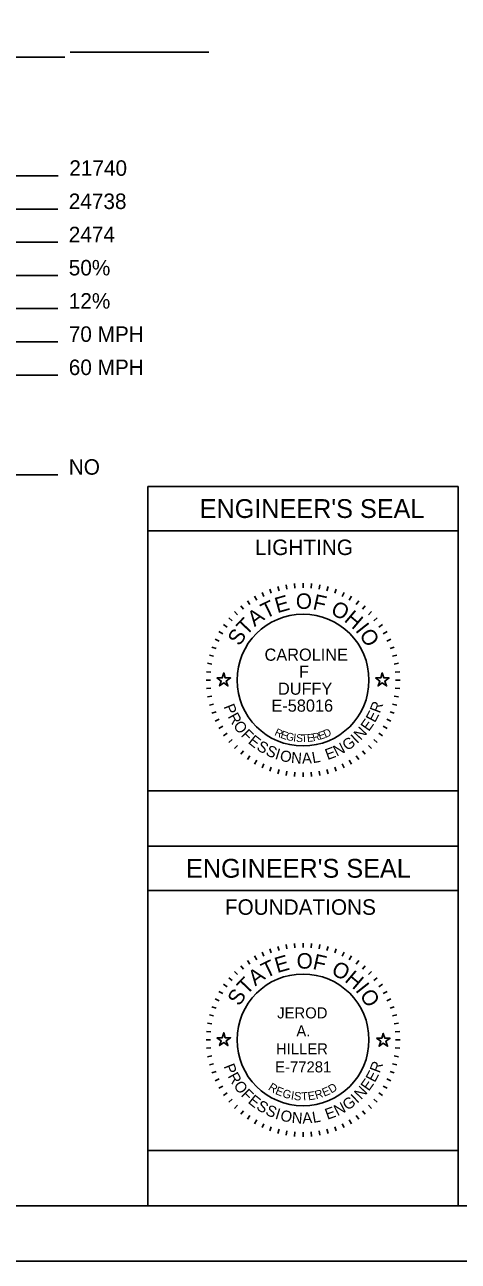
# Model space of a CAD drawing. Extents: x 0 to 51, y -1.2 to 22.
# Drawn here: x 7.34 to 11.25, y 0 to 11.17 of the extents above; entities that cross this region are included whole.
import ezdxf

# ---------------------------------------------------------------- set-up
doc = ezdxf.new("R2010")
doc.units = 0
for name, color, linetype in [('Default', 7, 'Continuous'), ('SH_Border', 7, 'Continuous'), ('SH_Cut_Line', 7, 'Continuous'), ('SH_Data', 7, 'Continuous'), ('SH_Text', 7, 'Continuous')]:
    doc.layers.add(name, color=color, linetype=linetype)

msp = doc.modelspace()

# ---------------------------------------------------------------- linework, layer by layer
at = {"layer": 'Default'}
for points in [[(9.074, 5.27), (9.121, 5.27), (9.135, 5.315), (9.149, 5.27), (9.196, 5.27), (9.158, 5.242), (9.173, 5.198), (9.135, 5.225), (9.097, 5.198), (9.112, 5.242)], [(10.504, 5.27), (10.551, 5.27), (10.565, 5.315), (10.579, 5.27), (10.626, 5.27), (10.588, 5.242), (10.603, 5.198), (10.565, 5.225), (10.527, 5.198), (10.542, 5.242)]]:
    msp.add_lwpolyline(points, close=True, dxfattribs=at)
at = {"layer": 'SH_Border'}
msp.add_lwpolyline([(1.5, 21.5), (33.5, 21.5), (33.5, 0.5), (1.5, 0.5)], close=True, dxfattribs=at)
at = {"layer": 'SH_Cut_Line'}
msp.add_lwpolyline([(0, 0), (34, 0), (34, 22), (0, 22)], close=True, dxfattribs=at)
at = {"layer": 'SH_Data'}
for p, q in [((8.45, 3.75), (8.45, 7)), ((8.45, 7), (11.25, 7)), ((11.25, 7), (11.25, 3.75)), ((8.45, 6.6), (11.25, 6.6)), ((9.48, 6.043), (9.497, 6.007)), ((9.551, 6.072), (9.564, 6.035)), ((9.624, 6.095), (9.634, 6.057)), ((9.698, 6.112), (9.705, 6.072)), ((9.774, 6.122), (9.777, 6.082)), ((9.85, 6.125), (9.85, 6.085)), ((9.926, 6.122), (9.923, 6.082)), ((10.002, 6.112), (9.995, 6.072)), ((10.076, 6.095), (10.066, 6.057)), ((10.149, 6.072), (10.136, 6.035)), ((10.22, 6.043), (10.203, 6.007)), ((9.348, 5.967), (9.371, 5.934)), ((9.413, 6.008), (9.433, 5.973)), ((10.287, 6.008), (10.267, 5.973)), ((10.352, 5.967), (10.329, 5.934)), ((11.25, 3.75), (11.25, 5.921)), ((9.18, 5.812), (9.21, 5.787)), ((9.231, 5.869), (9.26, 5.84)), ((9.288, 5.92), (9.313, 5.89)), ((10.412, 5.92), (10.387, 5.89)), ((10.469, 5.869), (10.44, 5.84)), ((10.52, 5.812), (10.49, 5.787)), ((9.133, 5.752), (9.166, 5.729)), ((10.567, 5.752), (10.534, 5.729)), ((9.057, 5.62), (9.093, 5.603)), ((9.092, 5.688), (9.127, 5.668)), ((10.608, 5.688), (10.573, 5.668)), ((10.643, 5.62), (10.607, 5.603)), ((9.005, 5.476), (9.043, 5.466)), ((9.028, 5.549), (9.065, 5.536)), ((10.672, 5.549), (10.635, 5.536)), ((10.695, 5.476), (10.657, 5.466)), ((8.988, 5.402), (9.028, 5.395)), ((10.712, 5.402), (10.672, 5.395)), ((8.978, 5.326), (9.018, 5.323)), ((10.722, 5.326), (10.682, 5.323)), ((8.975, 5.25), (9.015, 5.25)), ((8.978, 5.174), (9.018, 5.177)), ((10.722, 5.174), (10.682, 5.177)), ((10.725, 5.25), (10.685, 5.25)), ((8.988, 5.098), (9.028, 5.105)), ((9.005, 5.024), (9.043, 5.034)), ((10.695, 5.024), (10.657, 5.034)), ((10.712, 5.098), (10.672, 5.105)), ((9.028, 4.951), (9.065, 4.964)), ((10.672, 4.951), (10.635, 4.964)), ((9.057, 4.88), (9.093, 4.897)), ((9.092, 4.813), (9.127, 4.833)), ((10.608, 4.813), (10.573, 4.833)), ((10.643, 4.88), (10.607, 4.897)), ((9.133, 4.748), (9.166, 4.771)), ((9.18, 4.688), (9.21, 4.713)), ((10.52, 4.688), (10.49, 4.713)), ((10.567, 4.748), (10.534, 4.771)), ((9.231, 4.631), (9.26, 4.66)), ((9.288, 4.58), (9.313, 4.61)), ((10.412, 4.58), (10.387, 4.61)), ((10.469, 4.631), (10.44, 4.66)), ((9.348, 4.533), (9.371, 4.566)), ((9.413, 4.492), (9.433, 4.527)), ((9.48, 4.457), (9.497, 4.493)), ((10.22, 4.457), (10.203, 4.493)), ((10.287, 4.492), (10.267, 4.527)), ((10.352, 4.533), (10.329, 4.566)), ((9.551, 4.428), (9.564, 4.465)), ((9.624, 4.405), (9.634, 4.443)), ((9.698, 4.388), (9.705, 4.428)), ((9.774, 4.378), (9.777, 4.418)), ((9.85, 4.375), (9.85, 4.415)), ((9.926, 4.378), (9.923, 4.418)), ((10.002, 4.388), (9.995, 4.428)), ((10.076, 4.405), (10.066, 4.443)), ((10.149, 4.428), (10.136, 4.465)), ((11.25, 3.75), (8.45, 3.75)), ((8.45, 3.75), (8.45, 0.5)), ((11.25, 3.75), (8.45, 3.75)), ((8.45, 3.75), (11.25, 3.75)), ((11.25, 0.5), (11.25, 3.75)), ((11.25, 3.35), (8.45, 3.35)), ((9.48, 2.793), (9.497, 2.757)), ((9.551, 2.822), (9.564, 2.785)), ((9.624, 2.845), (9.634, 2.807)), ((9.698, 2.862), (9.705, 2.822)), ((9.774, 2.872), (9.777, 2.832)), ((9.85, 2.875), (9.85, 2.835)), ((9.926, 2.872), (9.923, 2.832)), ((10.002, 2.862), (9.995, 2.822)), ((10.076, 2.845), (10.066, 2.807)), ((10.149, 2.822), (10.136, 2.785)), ((10.22, 2.793), (10.203, 2.757)), ((9.348, 2.717), (9.371, 2.684)), ((9.413, 2.758), (9.433, 2.723)), ((10.287, 2.758), (10.267, 2.723)), ((10.352, 2.717), (10.329, 2.684)), ((9.231, 2.619), (9.26, 2.59)), ((9.288, 2.67), (9.313, 2.64)), ((10.412, 2.67), (10.387, 2.64)), ((10.469, 2.619), (10.44, 2.59)), ((9.133, 2.502), (9.166, 2.479)), ((9.18, 2.562), (9.21, 2.537)), ((10.52, 2.562), (10.49, 2.537)), ((10.567, 2.502), (10.534, 2.479)), ((9.057, 2.37), (9.093, 2.353)), ((9.092, 2.438), (9.127, 2.418)), ((10.608, 2.438), (10.573, 2.418)), ((10.643, 2.37), (10.607, 2.353)), ((9.028, 2.299), (9.065, 2.286)), ((10.672, 2.299), (10.635, 2.286)), ((8.988, 2.152), (9.028, 2.145)), ((9.005, 2.226), (9.043, 2.216)), ((10.695, 2.226), (10.657, 2.216)), ((10.712, 2.152), (10.672, 2.145)), ((8.978, 2.076), (9.018, 2.073)), ((10.722, 2.076), (10.682, 2.073)), ((8.975, 2), (9.015, 2)), ((8.978, 1.924), (9.018, 1.927)), ((10.722, 1.924), (10.682, 1.927)), ((10.725, 2), (10.685, 2)), ((8.988, 1.848), (9.028, 1.855)), ((10.712, 1.848), (10.672, 1.855)), ((9.005, 1.774), (9.043, 1.784)), ((9.028, 1.701), (9.065, 1.714)), ((10.672, 1.701), (10.635, 1.714)), ((10.695, 1.774), (10.657, 1.784)), ((9.057, 1.63), (9.093, 1.647)), ((9.092, 1.563), (9.127, 1.583)), ((10.608, 1.563), (10.573, 1.583)), ((10.643, 1.63), (10.607, 1.647)), ((9.133, 1.498), (9.166, 1.521)), ((9.18, 1.438), (9.21, 1.463)), ((10.52, 1.438), (10.49, 1.463)), ((10.567, 1.498), (10.534, 1.521)), ((9.231, 1.381), (9.26, 1.41)), ((9.288, 1.33), (9.313, 1.36)), ((10.412, 1.33), (10.387, 1.36)), ((10.469, 1.381), (10.44, 1.41)), ((9.348, 1.283), (9.371, 1.316)), ((9.413, 1.242), (9.433, 1.277)), ((9.48, 1.207), (9.497, 1.243)), ((10.22, 1.207), (10.203, 1.243)), ((10.287, 1.242), (10.267, 1.277)), ((10.352, 1.283), (10.329, 1.316)), ((9.551, 1.178), (9.564, 1.215)), ((9.624, 1.155), (9.634, 1.193)), ((9.698, 1.138), (9.705, 1.178)), ((9.774, 1.128), (9.777, 1.168)), ((9.85, 1.125), (9.85, 1.165)), ((9.926, 1.128), (9.923, 1.168)), ((10.002, 1.138), (9.995, 1.178)), ((10.076, 1.155), (10.066, 1.193)), ((10.149, 1.178), (10.136, 1.215)), ((11.25, 0.5), (8.45, 0.5))]:
    msp.add_line(p, q, dxfattribs=at)
for points in [[(11.25, 3.75), (11.25, 4.25), (8.45, 4.25), (8.45, 3.75)], [(8.45, 3.75), (8.45, 4.25), (11.25, 4.25), (11.25, 3.75)], [(9.074, 2.02), (9.121, 2.02), (9.135, 2.065), (9.149, 2.02), (9.196, 2.02), (9.158, 1.992), (9.173, 1.948), (9.135, 1.975), (9.097, 1.948), (9.112, 1.992)], [(10.513, 2.015), (10.56, 2.015), (10.574, 2.059), (10.589, 2.015), (10.635, 2.015), (10.598, 1.987), (10.612, 1.942), (10.574, 1.97), (10.536, 1.942), (10.551, 1.987)], [(11.25, 0.5), (11.25, 1), (8.45, 1), (8.45, 0.5)]]:
    msp.add_lwpolyline(points, close=True, dxfattribs=at)
for centre in [(9.85, 5.25), (9.85, 2)]:
    msp.add_circle(centre, 0.595, dxfattribs=at)
at = {"layer": 'SH_Text'}
for p, q in [((7.7, 10.877), (3.347, 10.877)), ((9, 10.922), (7.75, 10.922)), ((7.642, 9.806), (3.871, 9.806)), ((7.637, 9.506), (4.189, 9.506)), ((7.637, 9.206), (4.872, 9.206)), ((7.637, 8.906), (4.604, 8.906)), ((7.637, 8.606), (4.189, 8.606)), ((7.637, 8.306), (3.346, 8.306)), ((7.637, 8.006), (3.242, 8.006)), ((7.637, 7.106), (3.267, 7.106))]:
    msp.add_line(p, q, dxfattribs=at)

# ---------------------------------------------------------------- texts
at = {"layer": 'SH_Data'}
for s, height, p in [("ENGINEER'S SEAL", 0.17, (8.918, 6.715)), ('LIGHTING', 0.14, (9.416, 6.38)), ('CAROLINE', 0.11, (9.503, 5.425)), ('F', 0.11, (9.814, 5.272)), ('DUFFY', 0.11, (9.624, 5.118)), ('E-58016', 0.11, (9.565, 4.965)), ("ENGINEER'S SEAL", 0.17, (8.795, 3.465)), ('FOUNDATIONS', 0.14, (9.145, 3.13)), ('JEROD', 0.1, (9.617, 2.194)), ('A.', 0.1, (9.79, 2.031)), ('HILLER', 0.1, (9.606, 1.869)), ('E-77281', 0.1, (9.599, 1.706))]:
    msp.add_text(s, height=height, dxfattribs=at).set_placement(p)
for s, height, rotation, p in [('O', 0.14, 359.7812, (9.785, 5.894)), ('T', 0.14, 25.7167, (9.512, 5.802)), ('E', 0.14, 15.7571, (9.618, 5.854)), ('F', 0.14, 347.4362, (9.931, 5.892)), ('O', 0.14, 332.2586, (10.09, 5.852)), ('T', 0.14, 46.4344, (9.338, 5.646)), ('A', 0.14, 36.4747, (9.413, 5.728)), ('H', 0.14, 319.9136, (10.213, 5.786)), ('S', 0.14, 57.1924, (9.278, 5.551)), ('I', 0.14, 308.367, (10.316, 5.698)), ('O', 0.14, 303.1491, (10.352, 5.659)), ('P', 0.1, 291.494, (9.132, 5.012)), ('R', 0.1, 69.2322, (10.542, 4.945)), ('R', 0.1, 298.7311, (9.169, 4.922)), ('E', 0.1, 61.9951, (10.498, 4.86)), ('O', 0.1, 306.4666, (9.215, 4.838)), ('F', 0.1, 314.7068, (9.284, 4.748)), ('R', 0.07, 334.487, (9.587, 4.755)), ('D', 0.07, 23.3052, (10.051, 4.727)), ('N', 0.1, 47.0224, (10.37, 4.701)), ('E', 0.1, 54.758, (10.443, 4.781)), ('E', 0.1, 321.4393, (9.348, 4.685)), ('S', 0.1, 328.6764, (9.424, 4.625)), ('E', 0.07, 341.04, (9.641, 4.73)), ('G', 0.07, 347.4752, (9.691, 4.712)), ('I', 0.07, 353.7858, (9.759, 4.697)), ('S', 0.07, 356.8926, (9.786, 4.693)), ('T', 0.07, 3.0061, (9.836, 4.689)), ('E', 0.07, 6.0117, (9.889, 4.691)), ('R', 0.07, 11.9184, (9.942, 4.697)), ('E', 0.07, 17.6836, (10, 4.71)), ('G', 0.1, 35.0469, (10.248, 4.607)), ('I', 0.1, 43.287, (10.337, 4.671)), ('S', 0.1, 335.9134, (9.506, 4.577)), ('I', 0.1, 343.1505, (9.591, 4.54)), ('O', 0.1, 346.8859, (9.634, 4.525)), ('N', 0.1, 355.1261, (9.739, 4.502)), ('A', 0.1, 2.8617, (9.842, 4.494)), ('L', 0.1, 10.0987, (9.939, 4.499)), ('E', 0.1, 20.0742, (10.071, 4.527)), ('N', 0.1, 27.3113, (10.154, 4.558)), ('T', 0.14, 25.7167, (9.516, 2.554)), ('E', 0.14, 15.7571, (9.617, 2.603)), ('O', 0.14, 359.7812, (9.792, 2.644)), ('F', 0.14, 347.4362, (9.931, 2.642)), ('O', 0.14, 332.2586, (10.096, 2.598)), ('T', 0.14, 46.4344, (9.342, 2.4)), ('A', 0.14, 36.4747, (9.419, 2.482)), ('H', 0.14, 319.9136, (10.218, 2.532)), ('S', 0.14, 57.1924, (9.276, 2.298)), ('I', 0.14, 308.367, (10.317, 2.447)), ('O', 0.14, 303.1491, (10.356, 2.403)), ('P', 0.1, 291.494, (9.132, 1.762)), ('R', 0.1, 69.2322, (10.541, 1.694)), ('R', 0.1, 298.7311, (9.168, 1.673)), ('E', 0.1, 61.9951, (10.497, 1.609)), ('O', 0.1, 306.4666, (9.218, 1.585)), ('R', 0.075, 327.8239, (9.53, 1.554)), ('E', 0.075, 337.7777, (9.594, 1.513)), ('E', 0.075, 23.3052, (10.041, 1.486)), ('D', 0.075, 31.466, (10.105, 1.514)), ('N', 0.1, 47.0224, (10.374, 1.455)), ('E', 0.1, 54.758, (10.443, 1.531)), ('F', 0.1, 314.7068, (9.284, 1.498)), ('E', 0.1, 321.4393, (9.347, 1.435)), ('G', 0.075, 344.2727, (9.658, 1.485)), ('I', 0.075, 350.6464, (9.737, 1.463)), ('S', 0.075, 353.7858, (9.765, 1.458)), ('T', 0.075, 3.0061, (9.835, 1.451)), ('E', 0.075, 8.9826, (9.899, 1.453)), ('R', 0.075, 17.6836, (9.969, 1.463)), ('G', 0.1, 35.0469, (10.25, 1.358)), ('I', 0.1, 43.287, (10.338, 1.422)), ('S', 0.1, 328.6764, (9.422, 1.377)), ('S', 0.1, 335.9134, (9.504, 1.328)), ('I', 0.1, 343.1505, (9.592, 1.289)), ('O', 0.1, 346.8859, (9.638, 1.274)), ('N', 0.1, 355.1261, (9.745, 1.251)), ('A', 0.1, 2.8617, (9.846, 1.244)), ('L', 0.1, 10.0987, (9.942, 1.249)), ('E', 0.1, 20.0742, (10.07, 1.277)), ('N', 0.1, 27.3113, (10.16, 1.31))]:
    msp.add_text(s, height=height, rotation=rotation, dxfattribs=at).set_placement(p)
at = {"layer": 'SH_Text'}
for s, p in [('21740', (7.742, 9.806)), ('24738', (7.737, 9.506)), ('2474', (7.737, 9.206)), ('50%', (7.737, 8.906)), ('12%', (7.737, 8.606)), ('70 MPH', (7.737, 8.306)), ('60 MPH', (7.737, 8.006)), ('NO', (7.737, 7.106))]:
    msp.add_text(s, height=0.14, dxfattribs=at).set_placement(p)

doc.saveas('drawing.dxf')
